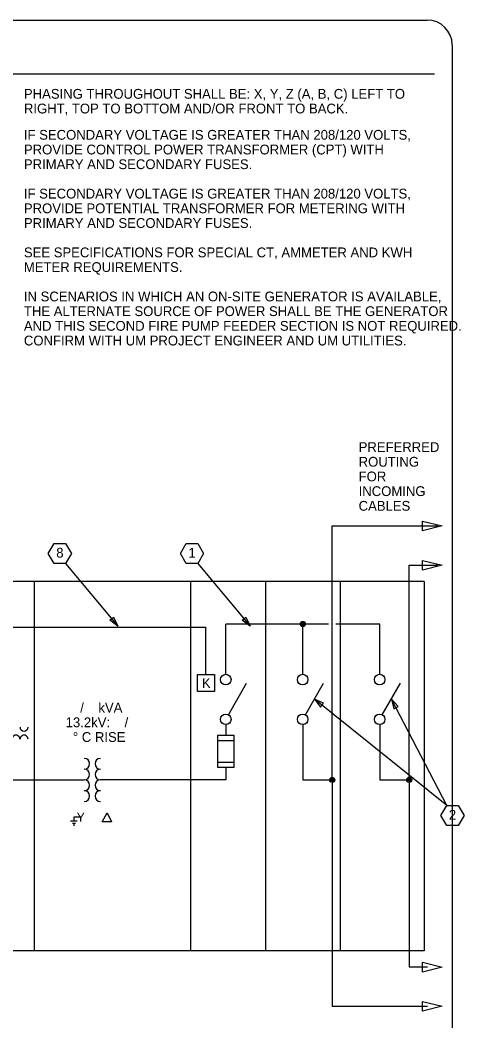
# Model space of a CAD drawing. Extents: x 10251 to 10396, y 10092 to 10197.
# Drawn here: x 10365.3 to 10395.5, y 10128.8 to 10196.9 of the extents above; entities that cross this region are included whole.
import ezdxf

# ---------------------------------------------------------------- set-up
doc = ezdxf.new("R2010")
doc.units = 0
for name, color, linetype in [('Default', 7, 'Continuous'), ('G-ANNO-TEXT', 7, 'Continuous'), ('G-ANNO-TTLB', 7, 'Continuous'), ('G-DETL-LINE', 7, 'Continuous'), ('G-DETL-OTLN', 7, 'Continuous'), ('G-DETL-PATT', 7, 'Continuous')]:
    doc.layers.add(name, color=color, linetype=linetype)

msp = doc.modelspace()

# ---------------------------------------------------------------- linework, layer by layer
at = {"layer": 'Default'}
msp.add_lwpolyline([(10395.509, 10142.807), (10395.116, 10142.128), (10394.332, 10142.128), (10393.94, 10142.807), (10394.332, 10143.487), (10395.116, 10143.487)], close=True, dxfattribs=at)
for centre, radius in [((10384.525, 10155.834), 0.174), ((10384.525, 10155.834), 0.0977), ((10384.525, 10155.834), 0.0326), ((10386.533, 10145.226), 0.174), ((10386.533, 10145.226), 0.0977), ((10386.533, 10145.226), 0.0326), ((10391.774, 10145.226), 0.0977), ((10391.774, 10145.226), 0.0326)]:
    msp.add_circle(centre, radius, dxfattribs=at)
at = {"layer": 'G-ANNO-TEXT'}
for p, q in [((10290.736, 10193.271), (10393.489, 10193.271)), ((10368.376, 10159.962), (10371.943, 10155.692)), ((10377.379, 10159.962), (10380.946, 10155.692)), ((10394.332, 10143.487), (10385.323, 10150.728)), ((10394.332, 10143.487), (10390.564, 10150.728)), ((10370.861, 10142.376), (10371.215, 10142.979)), ((10371.215, 10142.979), (10371.497, 10142.376)), ((10369.172, 10142.414), (10368.722, 10142.414)), ((10369.056, 10142.262), (10368.85, 10142.262)), ((10369.005, 10142.138), (10368.901, 10142.138)), ((10369.455, 10142.679), (10368.947, 10142.68)), ((10368.947, 10142.679), (10368.947, 10142.414)), ((10371.497, 10142.376), (10370.861, 10142.376))]:
    msp.add_line(p, q, dxfattribs=at)
for points in [[(10368.768, 10160.641), (10368.376, 10159.962), (10367.592, 10159.962), (10367.2, 10160.641), (10367.592, 10161.32), (10368.376, 10161.32)], [(10377.771, 10160.641), (10377.379, 10159.962), (10376.595, 10159.962), (10376.203, 10160.641), (10376.595, 10161.32), (10377.379, 10161.32)], [(10371.644, 10156.31), (10371.943, 10155.692), (10371.388, 10156.097)], [(10380.647, 10156.31), (10380.946, 10155.692), (10380.391, 10156.097)], [(10380.647, 10156.31), (10380.946, 10155.692), (10380.391, 10156.097)], [(10385.947, 10150.44), (10385.323, 10150.728), (10385.738, 10150.181)], [(10391.019, 10150.214), (10390.564, 10150.728), (10390.724, 10150.06)]]:
    msp.add_lwpolyline(points, close=True, dxfattribs=at)
at = {"layer": 'G-ANNO-TTLB'}
msp.add_line((10394.706, 10195.228), (10394.706, 10111.866), dxfattribs=at)
msp.add_lwpolyline([(10254.096, 10196.937), (10393.006, 10196.937)], dxfattribs=at)
msp.add_arc((10393.006, 10195.237), 1.7, 0, 90, dxfattribs=at)
at = {"layer": 'G-DETL-LINE'}
for p, q in [((10386.533, 10145.225), (10386.533, 10162.508)), ((10386.533, 10162.508), (10393.725, 10162.508)), ((10391.774, 10145.225), (10391.774, 10159.829)), ((10391.774, 10159.829), (10393.725, 10159.829)), ((10379.284, 10153.132), (10379.284, 10155.834)), ((10384.525, 10153.132), (10384.525, 10155.834)), ((10389.766, 10153.132), (10389.766, 10155.834)), ((10379.284, 10152.411), (10379.284, 10153.132)), ((10384.525, 10152.411), (10384.525, 10153.132)), ((10389.766, 10152.411), (10389.766, 10153.132)), ((10379.464, 10149.659), (10380.699, 10151.797)), ((10384.705, 10149.659), (10385.94, 10151.797)), ((10389.946, 10149.659), (10391.181, 10151.797)), ((10379.284, 10148.986), (10379.284, 10148.265)), ((10384.525, 10148.986), (10384.525, 10148.265)), ((10389.766, 10148.986), (10389.766, 10148.265)), ((10378.734, 10148.265), (10379.833, 10148.265)), ((10378.734, 10146.069), (10378.734, 10148.265)), ((10379.833, 10148.265), (10379.833, 10146.069)), ((10384.525, 10148.265), (10384.525, 10145.225)), ((10389.766, 10148.265), (10389.766, 10145.225)), ((10378.734, 10147.9), (10379.833, 10147.9)), ((10378.734, 10146.434), (10379.833, 10146.434)), ((10379.833, 10146.069), (10378.734, 10146.069)), ((10379.284, 10146.069), (10379.284, 10145.225)), ((10351.401, 10145.226), (10369.648, 10145.226)), ((10379.284, 10145.225), (10370.748, 10145.225)), ((10384.525, 10145.225), (10386.533, 10145.225)), ((10386.533, 10145.225), (10386.533, 10129.818)), ((10389.766, 10145.225), (10391.774, 10145.225)), ((10391.774, 10145.225), (10391.774, 10132.498)), ((10391.774, 10132.498), (10393.033, 10132.498)), ((10386.533, 10129.818), (10393.033, 10129.818))]:
    msp.add_line(p, q, dxfattribs=at)
for points in [[(10392.682, 10162.842), (10394.015, 10162.508), (10392.682, 10162.175)], [(10392.682, 10160.162), (10394.015, 10159.829), (10392.682, 10159.495)], [(10392.682, 10132.816), (10394.015, 10132.483), (10392.682, 10132.15)], [(10392.682, 10130.153), (10394.015, 10129.82), (10392.682, 10129.487)]]:
    msp.add_lwpolyline(points, close=True, dxfattribs=at)
for points in [[(10386.283, 10155.834), (10379.284, 10155.834)], [(10389.766, 10155.834), (10386.783, 10155.834)]]:
    msp.add_lwpolyline(points, dxfattribs=at)
for centre, radius in [((10379.284, 10152.05), 0.36), ((10384.525, 10152.05), 0.36), ((10389.766, 10152.05), 0.36), ((10379.284, 10149.347), 0.36), ((10384.525, 10149.347), 0.36), ((10389.766, 10149.347), 0.36), ((10391.774, 10145.226), 0.174)]:
    msp.add_circle(centre, radius, dxfattribs=at)
for centre, radius, start, end in [((10364.997, 10147.993), 0.275, 0.00003, 180.00003), ((10365.547, 10148.817), 0.275, 180.00003, 0.00003), ((10365.547, 10147.993), 0.275, 0.00003, 180.00003), ((10369.648, 10146.325), 0.366, 270.00003, 90.00003), ((10370.748, 10146.325), 0.366, 90.00003, 270.00003), ((10369.648, 10145.592), 0.366, 270.00003, 90.00003), ((10370.748, 10145.592), 0.366, 90.00003, 270.00003), ((10369.648, 10144.859), 0.366, 270.00003, 90.00003), ((10370.748, 10144.859), 0.366, 90.00003, 270.00003), ((10369.648, 10144.126), 0.366, 270.00003, 90.00003), ((10370.748, 10144.126), 0.366, 90.00003, 270.00003)]:
    msp.add_arc(centre, radius, start, end, dxfattribs=at)
at = {"layer": 'G-DETL-OTLN'}
for p, q in [((10392.803, 10158.727), (10327.51, 10158.727)), ((10366.228, 10158.727), (10366.228, 10133.6)), ((10376.893, 10158.727), (10376.893, 10133.6)), ((10381.987, 10158.727), (10381.987, 10133.6)), ((10387.081, 10158.727), (10387.081, 10133.6)), ((10392.803, 10158.727), (10392.803, 10133.6)), ((10392.803, 10133.6), (10327.51, 10133.6))]:
    msp.add_line(p, q, dxfattribs=at)
at = {"layer": 'G-DETL-PATT'}
msp.add_line((10377.931, 10152.392), (10377.931, 10155.619), dxfattribs=at)
msp.add_lwpolyline([(10352.344, 10147.535), (10352.344, 10155.619), (10377.931, 10155.619)], dxfattribs=at)
msp.add_lwpolyline([(10377.352, 10151.234), (10377.352, 10152.392), (10378.509, 10152.392), (10378.509, 10151.234)], close=True, dxfattribs=at)

# ---------------------------------------------------------------- texts
at = {"layer": 'Default'}
msp.add_text('2', height=0.667, dxfattribs=at).set_placement((10394.48, 10142.517))
at = {"layer": 'G-ANNO-TEXT'}
for s, height, p in [('PHASING THROUGHOUT SHALL BE: X, Y, Z (A, B, C) LEFT TO', 0.66667, (10365.537, 10191.58)), ('RIGHT, TOP TO BOTTOM AND/OR FRONT TO BACK.', 0.66667, (10365.537, 10190.58)), ('IF SECONDARY VOLTAGE IS GREATER THAN 208/120 VOLTS,', 0.66667, (10365.537, 10188.79)), ('PROVIDE CONTROL POWER TRANSFORMER (CPT) WITH', 0.66667, (10365.537, 10187.79)), ('PRIMARY AND SECONDARY FUSES. ', 0.66667, (10365.537, 10186.79)), ('IF SECONDARY VOLTAGE IS GREATER THAN 208/120 VOLTS,', 0.66667, (10365.537, 10184.79)), ('PROVIDE POTENTIAL TRANSFORMER FOR METERING WITH', 0.66667, (10365.537, 10183.79)), ('PRIMARY AND SECONDARY FUSES. ', 0.66667, (10365.537, 10182.79)), ('SEE SPECIFICATIONS FOR SPECIAL CT, AMMETER AND KWH', 0.66667, (10365.537, 10180.79)), ('METER REQUIREMENTS.', 0.66667, (10365.537, 10179.79)), ('IN SCENARIOS IN WHICH AN ON-SITE GENERATOR IS AVAILABLE,', 0.66667, (10365.537, 10177.79)), ('THE ALTERNATE SOURCE OF POWER SHALL BE THE GENERATOR', 0.66667, (10365.537, 10176.79)), ('AND THIS SECOND FIRE PUMP FEEDER SECTION IS NOT REQUIRED.', 0.66667, (10365.537, 10175.79)), ('CONFIRM WITH UM PROJECT ENGINEER AND UM UTILITIES.', 0.66667, (10365.537, 10174.79)), ('PREFERRED', 0.6667, (10388.334, 10167.542)), ('ROUTING', 0.6667, (10388.334, 10166.542)), ('FOR', 0.6667, (10388.334, 10165.542)), ('INCOMING', 0.6667, (10388.334, 10164.542)), ('CABLES', 0.6667, (10388.334, 10163.542)), ('8', 0.667, (10367.74, 10160.351)), ('1', 0.667, (10376.743, 10160.351)), ('    /    kVA', 0.66667, (10368.382, 10149.811)), ('13.2kV:    /    ', 0.66667, (10368.382, 10148.811)), ('  ° C RISE', 0.6667, (10368.382, 10147.811))]:
    msp.add_text(s, height=height, dxfattribs=at).set_placement(p)
msp.add_text('Y', height=0.617, rotation=360, dxfattribs=at).set_placement((10369.132, 10142.377))
at = {"layer": 'G-DETL-PATT'}
msp.add_text('K', height=0.667, rotation=360, dxfattribs=at).set_placement((10377.661, 10151.48))

doc.saveas('drawing.dxf')
